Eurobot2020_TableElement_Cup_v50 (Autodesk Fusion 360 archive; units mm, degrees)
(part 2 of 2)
sketch "Sketch1" plane through (0, 0, 0) normal (1, 0, 0) x axis (0, 1, 0)
  line L1 (0, 5.6673) -> (0, 0)
  line L2 (0, 150) -> (0, 5.6673)
  line L3 (150, 0) -> (-150, 0)
  line L4 (0, -150) -> (0, 0)
  line L5 (25, -137.7498) -> (25, 137.7498)
  line L6 (-25, -137.7498) -> (-25, 137.7498)
  line L7 (15, -139.1941) -> (15, 139.1941)
  line L8 (-15, 139.1941) -> (-15, -139.1941)
  line L9 (15, 20) -> (-15, 20)
  line L10 (-15, -20) -> (15, -20)
  circle C1 centre (0, 0) radius 150
  arc A1 centre (0, 0) radius 140 clockwise from (-15, 139.1941) to (15, 139.1941)
  arc A2 centre (0, 0) radius 140 clockwise from (-25, -137.7498) to (-25, 137.7498)
  arc A3 centre (0, 0) radius 140 clockwise from (25, 137.7498) to (25, -137.7498)
  arc A4 centre (0, 0) radius 140 clockwise from (15, -139.1941) to (-15, -139.1941)
  point P1 (0, 0)
  point P2 (0, 0)
  point P3 (0, 0)
  point P5 (0, 150)
  point P6 (-150, 0)
  point P7 (150, 0)
  point P10 (0, 77.8337)
  point P11 (0, 0)
  point P12 (0, -150)
  point P13 (0, 0)
  point P18 (0, 0)
  point P17 (-25, -137.7498)
  point P19 (-25, -137.7498)
  point P20 (0, 0)
  point P15 (25, -137.7498)
  point P21 (25, -137.7498)
  point P24 (0, -75)
  point P25 (0, 0)
  point P26 (-15, 20)
  point P27 (15, 20)
  point P28 (15, -20)
  point P29 (-15, -20)
  coincident P1 P2
  coincident P1 P3
  vertical L1
  coincident C1 P5
  parallel L1 L2
  coincident C1 P6
  coincident C1 P7
  horizontal L3
  coincident P2 L3
  midpoint L2 P10
  coincident P2 P11
  coincident C1 P12
  perpendicular L3 L4
  coincident P1 P13
  vertical L6
  coincident P2 P18
  coincident P17 P19
  coincident P2 P20
  coincident P15 P21
  equal A1 A2
  equal A1 A3
  midpoint L4 P24
  coincident P2 P25
  tangent A3 A4
  perpendicular L3 L7
  parallel L6 L8
  coincident L8 P26
  coincident L7 P27
  perpendicular L7 L9
  coincident L7 P28
  coincident L8 P29
  perpendicular L8 L10
  dimension "d1" diameter C1 = 300
  dimension "d11" distance C1 A3 = 10
  dimension "d13" distance L5 L7 = 10
  dimension "d14" distance L6 L8 = 10
  dimension "d15" distance P18 L7 = 15
  dimension "d16" distance P20 L8 = 15
  dimension "d17" distance P13 L10 = 20
  dimension "d18" distance P2 L9 = 20
extrude "Extrude1" new body sketch "Sketch1" profile of C1 A1 L5 L6 A2 A3 A4 L7 L8 L9 L10 along normal blind 20
extrude "Extrude1" new body sketch "Sketch1" profile of C1 A1 L5 L6 A2 A3 A4 L7 L8 L9 L10 against normal blind 3
extrude "Extrude1" sketch "Sketch1" profile of C1 A1 L5 L6 A2 A3 A4 L7 L8 L9 L10 blind 3
as_built_joint "As-built1"
hole "Hole1" HoleDepth 70 HoleDiameter 7 TipAngle 118
sketch "Sketch3" plane through (0, 0, 0) normal (1, 0, 0) x axis (0, 1, 0)
  point P1 (0, 0)
  point P2 (0, 0)
  coincident P1 P2
hole "Hole2" HoleDepth 70 HoleDiameter 6 TipAngle 118
sketch "Sketch1" plane through (23, 0, 0) normal (1, 0, 0) x axis (0, 1, 0)
  circle C1 centre (0, 0) radius 150
  point P1 (0, 0)
  point P3 (0, 0)
  coincident P1 P3
hole "Hole2" HoleDepth 70 HoleDiameter 6 TipAngle 118 CSDiameter 14 CSAngle 90
sketch "Sketch2" plane through (0, 0, 0) normal (1, 0, 0) x axis (0, 1, 0)
  circle C1 centre (0, 0) radius 3.5
  circle C2 centre (0, 0) radius 2
  point P1 (0, 0)
  point P2 (0, 0)
  coincident P1 P2
  concentric C1 C2
  dimension "d55" diameter C1 = 7
  dimension "d56" diameter C2 = 4
extrude "Extrude1" new body sketch "Sketch2" along normal blind 20
as_built_joint "As-built2"
sketch "Sketch1" plane through (0, 0, 0) normal (0, 1, 0) x axis (1, 0, 0)
  line L1 (22.3531, 0) -> (-23.5815, 0)
  line L2 (22.3531, -4.2842) -> (22.3531, 0)
  line L3 (20, -1.7) -> (22.3531, -4.2842)
  line L4 (-23.5815, -1.7) -> (20, -1.7)
  line L5 (-23.5815, 0) -> (-23.5815, -1.7)
  line L6 (20, -150) -> (20, 150)
  point P1 (0, 0)
  point P5 (20, -1.7)
  horizontal L1
  perpendicular L1 L2
  perpendicular L2 L4
  coincident P1 L1
  coincident P5 L6
  vertical L5
  dimension "d59" distance L1 L4 = 1.7
revolve "Revolve1" sketch "Sketch1" AlongAngle 360
thread "Thread1" ThreadOffset 0 ThreadLength 21
sketch "Sketch2" plane through (0, 0, 0) normal (0, 1, 0) x axis (1, 0, 0)
  line L1 (-13.9609, -1.9748) -> (-23.5815, 0)
  line L2 (-23.5815, -1.9748) -> (-13.9609, -1.9748)
  line L3 (-23.5815, 0) -> (-23.5815, -1.9748)
  line L4 (-23.5815, 0) -> (0, 0)
  line L5 (-23.5815, 0.8397) -> (-23.5815, -0.8535)
  point P1 (0, 0)
  point P5 (0, 0)
  point P2 (-23.5815, 0)
  vertical L3
  horizontal L2
  coincident P1 P5
  horizontal L4
  coincident P2 L5
revolve "Revolve2" sketch "Sketch2" AlongAngle 360
offset_faces "OffsetFaces2" distance -0.43
offset_faces "OffsetFaces3" distance -1
sketch "Sketch3" plane through (22.3531, 0, 0) normal (1, 0, 0) x axis (0, 1, 0)
  line L1 (0, 2) -> (0, 0)
  line L2 (-0.4, 2) -> (0, 2)
  line L3 (-0.4, 0.4) -> (-0.4, 2)
  line L4 (-2, 0.4) -> (-0.4, 0.4)
  line L5 (-2, 0) -> (-2, 0.4)
  line L6 (0, 0) -> (-2, 0)
  line L7 (0.4, 0.4) -> (0.4, 2)
  line L8 (2, 0.4) -> (0.4, 0.4)
  line L9 (2, 0) -> (2, 0.4)
  line L10 (0.4, 2) -> (0, 2)
  line L11 (0.4, -2) -> (0, -2)
  line L12 (0.4, -0.4) -> (0.4, -2)
  line L13 (2, -0.4) -> (0.4, -0.4)
  line L14 (2, 0) -> (2, -0.4)
  line L15 (-0.4, -2) -> (0, -2)
  line L16 (-0.4, -0.4) -> (-0.4, -2)
  line L17 (-2, -0.4) -> (-0.4, -0.4)
  line L18 (-2, 0) -> (-2, -0.4)
  circle C1 centre (0, 0) radius 2.7989
  point P2 (0, 0)
  point P3 (0, 0)
  point P4 (0, 2)
  point P13 (0, 2)
  point P5 (-0.4, 2)
  point P9 (0.4, 2)
  point P6 (-0.4, 0.4)
  point P10 (0.4, 0.4)
  point P7 (-2, 0.4)
  point P11 (2, 0.4)
  point P8 (-2, 0)
  point P12 (2, 0)
  point P19 (0, -2)
  point P20 (-0.4, -2)
  point P21 (-0.4, -0.4)
  point P22 (-2, -0.4)
  point P23 (-2, 0)
  point P15 (0.4, -2)
  point P16 (0.4, -0.4)
  point P17 (2, -0.4)
  point P18 (2, 0)
  point P14 (0, -2)
  coincident P2 P3
  vertical L1
  perpendicular L1 L2
  perpendicular L2 L3
  perpendicular L1 L4
  perpendicular L2 L5
  horizontal L6
  equal L1 L6
  equal L2 L5
  symmetric P4 L1 P13
  symmetric L1 P5 P9
  symmetric L1 P6 P10
  symmetric L1 P7 P11
  symmetric L1 P8 P12
  symmetric P4 L6 P19
  symmetric P5 L6 P20
  symmetric P6 L6 P21
  symmetric P7 L6 P22
  symmetric P8 L6 P23
  symmetric L6 P9 P15
  symmetric L6 P10 P16
  symmetric L6 P11 P17
  symmetric L6 P12 P18
  symmetric L6 P13 P14
  dimension "d69" distance P4 P5 = 0.4
  dimension "d70" distance P7 P8 = 0.4
  dimension "d71" distance P3 P4 = 2
extrude "Extrude2" cut sketch "Sketch3" profile of L2 L3 L4 L5 L7 L8 L9 L10 L11 L12 L13 L14 L15 L16 L17 L18 against normal blind 1 taper -25
joint "Assemble1" alignAngle 0 alignOffsetX 0 alignOffsetY 0 alignOffsetZ 0.5
sketch "Sketch1" plane through (-3, 0, 0) normal (-1, 0, 0) x axis (0, -1, 0)
  circle C1 centre (0, 0) radius 3
  circle C2 centre (0, 0) radius 150
  circle C3 centre (0, 0) radius 5
  circle C4 centre (0, 0) radius 2
  point P1 (0, 0)
  point P3 (0, 0)
  coincident P1 P3
  concentric C1 C4
  dimension "d86" diameter C4 = 4
  dimension "d87" diameter C3 = 10
extrude "Extrude1" new body sketch "Sketch1" profile of C1 C3 C4 along normal blind 0.8
extrude "Extrude2" new body of existing geometry blind 0.8
as_built_joint "As-built3"
sketch "Sketch1" plane through (23, 0, 0) normal (1, 0, 0) x axis (0, 1, 0)
  circle C1 centre (0, 0) radius 150
extrude "Extrude1" new body sketch "Sketch1" along normal blind 0.3
decal "Decal1"
sketch "Sketch1" plane through (0, 0, 0) normal (1, 0, 0) x axis (0, 1, 0)
  line L1 (0, 32.5) -> (0, 0)
  line L2 (0, -127.5) -> (0, 0)
  line L3 (-15, 20) -> (15, 20)
  circle C1 centre (0, 32.5) radius 12.5
  circle C2 centre (0, -127.5) radius 12.5
  arc A1 centre (0, 0) radius 140 clockwise from (15, -139.1941) to (-15, -139.1941)
  point P1 (0, 0)
  point P2 (0, 0)
  point P3 (0, 32.5)
  point P4 (0, 32.5)
  point P5 (0, 0)
  point P6 (0, -127.5)
  point P7 (0, -127.5)
  point P8 (0, -140)
  point P9 (0, 20)
  coincident P1 P2
  vertical L1
  coincident P3 P4
  coincident P1 P5
  parallel L1 L2
  coincident P6 P7
  equal C1 C2
  coincident C2 P8
  coincident C1 P9
  coincident L1 P9
  coincident P9 L3
  coincident L2 P8
  coincident P8 A1
  dimension "d94" diameter C1 = 25
extrude "Extrude1" new body sketch "Sketch1" profile of C1 C2 along normal blind 18
as_built_joint "As-built4"
split_face "SplitFace1"
split_face "SplitFace1"
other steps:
split_face "SplitFace1"
split_face "SplitFace1"
create_component "CreateComponent1"
create_component "CreateComponent2"
create_component "CreateComponent3"
create_component "CreateComponent4"
create_component "CreateComponent5"
joint_origin "JointOrigin1" OffsetX 0 OffsetY 0 OffsetZ 0 AngleZ 0
joint_origin "JointOrigin1" OffsetX 0 OffsetY 0 OffsetZ 0 AngleZ 0
create_component "CreateComponent6"
create_component "CreateComponent7"
create_component "CreateComponent8"

design "Edge Beacon Right" references "EdgeBeacons_Base", "EdgeBeacons_LargeBorder", "EdgeBeacons_SmallBorder"
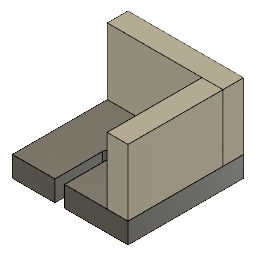
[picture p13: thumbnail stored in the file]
component_insert "Component Insert1"
ground "Ground1"
component_insert "Component Insert2"
component_insert "Component Insert4"
joint "Assemble1" OffsetX 0 OffsetY 0 OffsetZ 0 AngleZ 0 OffsetX 0 OffsetY 0 OffsetZ 0 AngleZ 0 alignAngle -90 alignOffsetX 0 alignOffsetY 0 alignOffsetZ 0
joint "Assemble2" OffsetX 0 OffsetY 0 OffsetZ 0 AngleZ 0 OffsetX 0 OffsetY 0 OffsetZ 0 AngleZ 0 alignAngle 0 alignOffsetX 0 alignOffsetY 0 alignOffsetZ 0

design "MiddleBeaconTop"
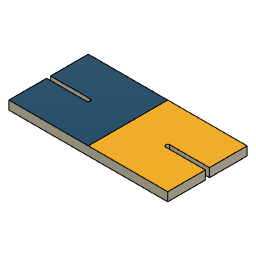
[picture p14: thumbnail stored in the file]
work_plane "WorkPlane1" AlongDistance 1000
sketch "Sketch1" plane through (0, 1000, 0) normal (0, 1, 0) x axis (1, 0, 0)
  line L1 (200, -100) -> (-200, -100)
  line L2 (200, 100) -> (200, -100)
  line L3 (-200, 100) -> (200, 100)
  line L4 (-200, -100) -> (-200, 100)
  line L5 (200, 100) -> (-200, -100)
  line L6 (-200, 100) -> (200, -100)
  line L7 (-100, -5) -> (-200, -5)
  line L8 (-200, 5) -> (-100, 5)
  line L9 (-100, 0) -> (-200, 0)
  line L10 (100, 5) -> (200, 5)
  line L11 (200, -5) -> (100, -5)
  line L12 (100, 0) -> (200, 0)
  arc A1 centre (-100, 0) radius 5 clockwise from (-100, 5) to (-100, -5)
  arc A2 centre (-200, 0) radius 5 clockwise from (-200, -5) to (-200, 5)
  arc A3 centre (100, 0) radius 5 clockwise from (100, -5) to (100, 5)
  arc A4 centre (200, 0) radius 5 clockwise from (200, 5) to (200, -5)
  point P6 (0, 0)
  point P1 (0, 0)
  point P11 (-200, 0)
  point P17 (200, 0)
  point P4 (200, 100)
  point P5 (-200, 100)
  point P3 (200, -100)
  point P12 (-100, 0)
  perpendicular L1 L2
  parallel L1 L3
  parallel L2 L4
  horizontal L1
  coincident L5 P6
  coincident L6 P6
  coincident P1 P6
  tangent L7 A1
  tangent A1 L8
  parallel L7 L8
  tangent L8 A2
  tangent L7 A2
  perpendicular L4 L9
  midpoint L4 P11
  tangent L10 A3
  tangent A3 L11
  parallel L10 L11
  tangent L11 A4
  tangent L10 A4
  perpendicular L2 L12
  midpoint L2 P17
  equal A1 A3
  equal L9 L12
  dimension "d2" distance P4 P5 = 400
  dimension "d3" distance P3 P4 = 200
  dimension "d4" distance P11 P12 = 100
  dimension "d5" radius A1 = 5
extrude "Extrude1" new body sketch "Sketch1" profile of L1 L2 L3 L4 L7 A1 L8 L10 A3 L11 against normal blind 22
work_plane "WorkPlane2"
split_face "SplitFace1"

design "MiddleBeaconVertSupport2"
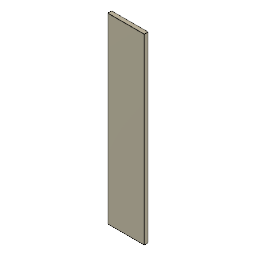
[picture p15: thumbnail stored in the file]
sketch "Sketch1"
  dimension "d1" = 1000
  dimension "d2" = 200
extrude "Extrude1" new body sketch "Sketch1" distance 22

design "manchonBleu"
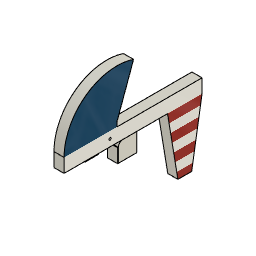
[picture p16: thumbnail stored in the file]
sketch "Sketch1" plane through (0, 0, 0) normal (1, 0, 0) x axis (0, 1, 0)
  line L1 (15, 15) -> (15, 25)
  line L2 (200, 15) -> (15, 15)
  line L3 (-100, -15) -> (125, -15)
  line L4 (-100, 15) -> (-100, -15)
  line L5 (200, 15) -> (200, -15)
  line L6 (177.5, -150) -> (200, -15)
  line L7 (147.5, -150) -> (177.5, -150)
  line L8 (125, -15) -> (147.5, -150)
  line L9 (0, 0) -> (200, 0)
  line L10 (15, 15) -> (-15, 15)
  line L11 (0, 15) -> (0, 0)
  line L12 (51.101, 124.1866) -> (15, 25)
  circle C1 centre (0, 0) radius 2.5
  circle C2 centre (15, 15) radius 115
  point P1 (0, 0)
  point P2 (0, 0)
  point P13 (200, 0)
  point P14 (0, 0)
  point P15 (0, 0)
  point P16 (0, 15)
  point P9 (-100, 15)
  point P5 (15, 15)
  point P17 (15, 15)
  point P18 (51.101, 124.1866)
  point P7 (125, -15)
  point P10 (200, -15)
  point P11 (177.5, -150)
  point P12 (147.5, -150)
  point P8 (-100, -15)
  point P4 (15, 25)
  coincident P1 P2
  perpendicular L1 L2
  horizontal L3
  perpendicular L3 L4
  vertical L5
  equal L4 L5
  parallel L3 L7
  equal L6 L8
  midpoint L5 P13
  coincident P1 P14
  horizontal L9
  coincident P1 P15
  midpoint L10 P16
  vertical L11
  coincident L2 P9
  horizontal L2
  horizontal L10
  equal L4 L10
  coincident P5 P17
  coincident P9 C2
  coincident C2 P18
  dimension "d1" diameter C1 = 5
  dimension "d2" distance P1 L4 = 100
  dimension "d4" distance P2 L5 = 200
  dimension "d8" distance P7 P10 = 75
  dimension "d9" distance P11 P12 = 30
  dimension "d11" distance P8 P9 = 30
  dimension "d12" distance P4 P5 = 10
  dimension "d22" distance L7 L9 = 150
  dimension "d23" angle L2 L12 = 70
  dimension "d36" OffsetX = 0
  dimension "d37" OffsetY = 0
  dimension "d38" OffsetZ = 0
  dimension "d39" AngleZ = 0
  dimension "d48" OffsetX = 0
  dimension "d49" OffsetY = 0
  dimension "d50" OffsetZ = 0
  dimension "d51" AngleZ = 0
extrude "Extrude1" new body sketch "Sketch1" profile of C1 L1 L2 L3 L4 L5 L6 L7 L8 C2 L12 along normal blind 22
sketch "Sketch1" plane through (0, 0, 0) normal (1, 0, 0) x axis (0, 0, -1)
  line L1 (55, 15) -> (15, 15)
  line L2 (55, 55) -> (55, 15)
  line L3 (15, 55) -> (55, 55)
  line L4 (15, 15) -> (15, 55)
  line L5 (15, -100) -> (15, 125)
  line L6 (25, 15) -> (15, 15)
  arc A1 centre (25, 25) radius 10 clockwise from (25, 15) to (15, 25)
  point P8 (25, 15)
  point P9 (15, 25)
  point P1 (0, 0)
  horizontal L1
  vertical L2
  horizontal L3
  vertical L4
  coincident L1 P8
  perpendicular L5 L6
  tangent L6 A1
  coincident L4 P9
  tangent L4 A1
  dimension "d24" distance P1 L1 = 15
  dimension "d25" distance P1 L4 = 15
  dimension "d26" distance P1 L5 = 15
  dimension "d27" distance L4 P8 = 10
  dimension "d28" distance L1 L3 = 40
  dimension "d29" distance L2 L4 = 40
  dimension "d32" OffsetX = 0
  dimension "d33" OffsetY = 0
  dimension "d34" OffsetZ = 0
  dimension "d35" AngleZ = 0
  dimension "d44" OffsetX = 0
  dimension "d45" OffsetY = 0
  dimension "d46" OffsetZ = 0
  dimension "d47" AngleZ = 0
extrude "Extrude1" new body sketch "Sketch1" profile of L1 L2 L3 L4 L5 A1 along normal blind 22
joint "Assemble1" alignAngle 0 alignOffsetX -25 alignOffsetY -28 alignOffsetZ 0
decal "Decal1"
decal "Decal2"
sketch "Sketch1" plane through (0, 18, 0) normal (0, -1, 0) x axis (1, 0, 0)
  line L1 (0, -55) -> (0, -25)
  line L2 (22, -55) -> (0, -55)
  line L3 (22, -25) -> (22, -55)
  line L4 (0, -25) -> (22, -25)
extrude "Extrude1" new body sketch "Sketch1" along normal blind 1.5 named "d52_1"
sketch "Sketch2" plane through (0, 0, -15) normal (0, 0, -1) x axis (1, 0, 0)
  line L1 (0, -125) -> (0, 100)
  line L2 (22, -125) -> (0, -125)
  line L3 (22, 100) -> (22, -125)
  line L4 (0, 100) -> (22, 100)
  line L5 (0, 55) -> (0, 25)
  line L6 (22, 55) -> (0, 55)
  line L7 (22, 25) -> (22, 55)
  line L8 (0, 25) -> (22, 25)
extrude "Extrude2" new body sketch "Sketch2" profile of L1 L3 L5 L6 L7 L8 along normal blind 1.5 named "d63_1"
joint_origin "JointOrigin1" OffsetX 0 named "d66_1" OffsetY 0 named "d67_1" OffsetZ 0 named "d68_1" AngleZ 0 named "d69_1"
joint_origin "JointOrigin2" OffsetX 0 named "d78_1" OffsetY 0 named "d79_1" OffsetZ 0 named "d80_1" AngleZ 0 named "d81_1"
remove_body "RemoveBody1"
joint "Assemble2" alignAngle 0 alignOffsetX 0 alignOffsetY 0 alignOffsetZ 0
base_feature "Base Feature"
joint "Assemble3" alignAngle 0 alignOffsetX 0 alignOffsetY 45 alignOffsetZ 0
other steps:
create_component "CreateComponent1"
create_component "CreateComponent2"
joint_origin "JointOrigin3" OffsetX 0 OffsetY 0 OffsetZ 0 AngleZ 0
joint_origin "JointOrigin3" OffsetX 0 OffsetY 0 OffsetZ 0 AngleZ 0
create_component "CreateComponent3"
joint_origin "JointOrigin1" OffsetX 0 OffsetY 0 OffsetZ 0 AngleZ 0
joint_origin "JointOrigin3" OffsetX 0 OffsetY 0 OffsetZ 0 AngleZ 0
joint_origin "JointOrigin4" OffsetX 0 OffsetY 0 OffsetZ 0 AngleZ 0
joint_origin "JointOrigin4" OffsetX 0 OffsetY 0 OffsetZ 0 AngleZ 0

design "Rocher"
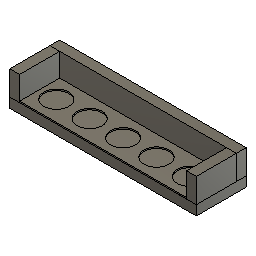
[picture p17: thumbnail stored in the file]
sketch "Sketch1" plane through (0, 0, 0) normal (0, 1, 0) x axis (1, 0, 0)
  line L1 (209.5, 0) -> (-209.5, 0)
  line L2 (209.5, 112) -> (209.5, 0)
  line L3 (-209.5, 112) -> (209.5, 112)
  line L4 (-209.5, 0) -> (-209.5, 112)
  point P6 (0, 0)
  horizontal L1
  vertical L2
  horizontal L3
  vertical L4
  coincident L1 P6
  dimension "d11" distance L2 L4 = 419 (= "375 mm + ( ( 22 * 2 ) * 1 mm )")
  dimension "d12" distance L2 P6 = 209.5 (= "d11 / 2")
  dimension "d13" distance L1 L3 = 112 (= "90 mm + 22 mm")
extrude "Extrude1" new body sketch "Sketch1" against normal blind 22
sketch "Sketch1" plane through (0, 0, 0) normal (0, 1, 0) x axis (-1, 0, 0)
  line L1 (-209.5, -112) -> (209.5, -112)
  line L2 (-209.5, -90) -> (-209.5, -112)
  line L3 (209.5, -90) -> (-209.5, -90)
  line L4 (209.5, -112) -> (209.5, -90)
  line L5 (-209.5, -112) -> (-209.5, 0)
  line L6 (209.5, 0) -> (209.5, -112)
  line L7 (209.5, -112) -> (-209.5, -112)
  horizontal L1
  vertical L2
  horizontal L3
  vertical L4
  collinear L2 L5
  collinear L4 L6
  collinear L1 L7
  dimension "d17" distance L1 L3 = 22
extrude "Extrude1" new body sketch "Sketch1" along normal blind 55
sketch "Sketch1" plane through (0, 0, 0) normal (0, 1, 0) x axis (-1, 0, 0)
  line L1 (-147, 0) -> (147, 0)
  line L2 (147, -90) -> (125, -90)
  line L3 (147, 0) -> (147, -90)
  line L4 (125, 0) -> (147, 0)
  line L5 (125, -90) -> (125, 0)
  line L6 (-147, 0) -> (147, 0)
  line L7 (147, -112) -> (-147, -112)
  line L8 (147, 0) -> (147, -112)
  line L9 (147, -90) -> (-147, -90)
  line L10 (147, 0) -> (147, -112)
  line L11 (-147, -112) -> (-147, 0)
  line L12 (147, -112) -> (-147, -112)
  horizontal L2
  vertical L3
  horizontal L4
  vertical L5
  collinear L4 L6
  collinear L3 L8
  collinear L2 L9
  dimension "d20" distance L3 L5 = 22
extrude "Extrude1" new body sketch "Sketch1" profile of L1 L2 L3 L4 L5 L6 L8 L9 L10 along normal blind 55
sketch "Sketch1" plane through (0, 0, 0) normal (0, 1, 0) x axis (-1, 0, 0)
  line L1 (209.5, 0) -> (209.5, -112)
  line L2 (-209.5, 0) -> (209.5, 0)
  line L3 (-209.5, -112) -> (-209.5, 0)
  line L4 (209.5, -112) -> (-209.5, -112)
  line L5 (-187.5, -90) -> (-209.5, -90)
  line L6 (-187.5, 0) -> (-187.5, -90)
  line L7 (-209.5, 0) -> (-187.5, 0)
  line L8 (-209.5, -90) -> (-209.5, 0)
  line L9 (209.5, -90) -> (-209.5, -90)
  horizontal L5
  vertical L6
  horizontal L7
  vertical L8
  collinear L2 L7
  collinear L5 L9
  collinear L3 L8
  dimension "d23" distance L6 L8 = 22
extrude "Extrude1" new body sketch "Sketch1" profile of L2 L3 L5 L6 L7 L8 L9 along normal blind 55
joint "Assemble1" alignAngle 0 alignOffsetX 0 alignOffsetY 0 alignOffsetZ 0
joint "Assemble2" alignAngle 0 alignOffsetX 0 alignOffsetY 0 alignOffsetZ 0
joint "Assemble3" alignAngle 0 alignOffsetX 0 alignOffsetY 0 alignOffsetZ 0
ground "Ground1"
sketch "Sketch1" plane through (0, 0, 0) normal (0, 1, 0) x axis (-1, 0, 0)
  line L1 (209.5, 0) -> (209.5, -112)
  line L2 (-209.5, 0) -> (209.5, 0)
  line L3 (-209.5, -112) -> (-209.5, 0)
  line L4 (209.5, -112) -> (-209.5, -112)
  line L5 (-209.5, -90) -> (209.5, -90)
  line L6 (187.5, -90) -> (187.5, 0)
  line L7 (-187.5, 0) -> (-187.5, -90)
  circle C1 centre (150, -45) radius 28
  circle C2 centre (75, -45) radius 28
  circle C3 centre (0, -45) radius 28
  circle C4 centre (-75, -45) radius 28
  circle C5 centre (-150, -45) radius 28
  point P12 (150, -45)
  point P13 (75, -45)
  point P14 (0, -45)
  point P15 (-75, -45)
  point P16 (-150, -45)
  dimension "d62" diameter C1 = 56
  dimension "d67" distance L6 P12 = 37.5
  dimension "d68" distance P12 P13 = 75 (= "d67 * 2")
  dimension "d69" distance P13 P14 = 75 (= "d68")
  dimension "d70" distance P14 P15 = 75 (= "d69")
  dimension "d72" distance L2 P12 = 45
  dimension "d73" distance L2 P13 = 45
  dimension "d74" distance L2 P14 = 45
  dimension "d75" distance L2 P15 = 45
  dimension "d90" diameter C5 = 56 (= "d62")
  dimension "d91" distance P15 P16 = 75
  dimension "d92" distance L7 P16 = 37.5
  dimension "d93" diameter C2 = 56 (= "d62")
  dimension "d94" diameter C3 = 56 (= "d62")
  dimension "d95" diameter C4 = 56
extrude "Extrude1" new body sketch "Sketch1" profile of L2 L5 L6 L7 C1 C2 C3 C4 C5 along normal blind 3
joint "Assemble4" alignAngle 180 alignOffsetX 0 alignOffsetY 0 alignOffsetZ 0
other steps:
create_component "CreateComponent1"
create_component "CreateComponent2"
create_component "CreateComponent3"
create_component "CreateComponent4"
joint_origin "JointOrigin1" OffsetX 0 OffsetY 0 OffsetZ 0 AngleZ 0
joint_origin "JointOrigin1" OffsetX 0 OffsetY 0 OffsetZ 0 AngleZ 0
joint_origin "JointOrigin1" OffsetX 0 OffsetY 0 OffsetZ 0 AngleZ 0
joint_origin "JointOrigin2" OffsetX 0 OffsetY 0 OffsetZ 0 AngleZ 0
joint_origin "JointOrigin1" OffsetX 0 OffsetY 0 OffsetZ 0 AngleZ 0
joint_origin "JointOrigin3" OffsetX 0 OffsetY 0 OffsetZ 0 AngleZ 0
create_component "CreateComponent5"
joint_origin "JointOrigin1" OffsetX 0 OffsetY 0 OffsetZ 0 AngleZ 0
joint_origin "JointOrigin2" OffsetX 0 OffsetY 0 OffsetZ 0 AngleZ 0

design "Balise Rouge"
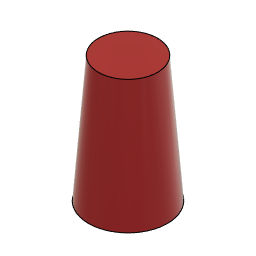
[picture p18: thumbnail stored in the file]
sketch "Sketch1" plane through (0, 0, 0) normal (1, 0, 0) x axis (0, 0, -1)
  line L1 (-36, 0) -> (0, 0)
  line L2 (-27, 115) -> (-36, 0)
  line L3 (0, 115) -> (-27, 115)
  line L4 (0, 0) -> (0, 115)
  line L5 (-25.6128, 113.5) -> (0, 113.5)
  line L6 (-34.4954, 0) -> (-25.6128, 113.5)
  line L7 (0, 0) -> (-34.4954, 0)
  point P1 (0, 0)
  point P2 (0, 0)
  point P6 (0, 0)
  point P7 (0, 113.5)
  point P10 (0, 0)
  point P4 (-27, 115)
  point P5 (0, 115)
  point P3 (-36, 0)
  coincident P1 P2
  horizontal L1
  parallel L1 L3
  coincident P1 P6
  perpendicular L1 L4
  coincident L4 P7
  perpendicular L4 L5
  coincident L4 P10
  perpendicular L4 L7
  collinear L1 L7
  parallel L2 L6
  dimension "d1" distance P4 P5 = 27 (= "( 54 / 2 ) * 1 mm")
  dimension "d2" distance L1 L3 = 115
  dimension "d3" distance P2 P3 = 36 (= "( 72 / 2 ) * 1 mm")
  dimension "d5" distance L3 L5 = 1.5
  dimension "d6" distance L2 L6 = 1.5
revolve "Revolve1" sketch "Sketch1" AlongAngle 360

design "taquet"
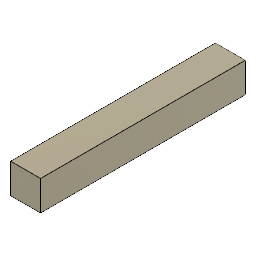
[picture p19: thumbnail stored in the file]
sketch "Sketch1" plane through (0, 0, 0) normal (0, 1, 0) x axis (1, 0, 0)
  line L1 (11, 150) -> (-11, 150)
  line L2 (11, 0) -> (11, 150)
  line L3 (11, 150) -> (-11, 0)
  line L4 (-11, 150) -> (-11, 0)
  point P1 (0, 0)
  horizontal L1
  vertical L2
  horizontal L3
  vertical L4
  coincident P1 L3
  dimension "d1" distance L2 L4 = 22
  dimension "d2" distance P1 L4 = 11 (= "d1 / 2")
  dimension "d3" = 150
extrude "Extrude1" new body sketch "Sketch1" along normal blind 22

design "ROUE_MINI_V3_ASSEMBLAGE" references "ROUE_V3"
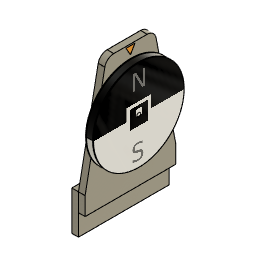
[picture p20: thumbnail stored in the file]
sketch "Sketch1" plane through (0, 0, 0) normal (1, 0, 0) x axis (0, 1, 0)
  line L1 (-150, 0) -> (0, 0)
  line L2 (0, 420) -> (-80, 420)
  line L3 (0, 0) -> (0, 420)
  line L4 (-150, 60) -> (-80, 420)
  line L5 (-150, 0) -> (-150, 60)
  line L6 (150, 0) -> (0, 0)
  line L7 (150, 0) -> (150, 60)
  line L8 (150, 60) -> (80, 420)
  line L9 (0, 420) -> (80, 420)
  point P1 (0, 0)
  point P2 (0, 0)
  point P6 (0, 0)
  point P8 (0, 0)
  point P3 (-150, 0)
  point P9 (150, 0)
  point P4 (-80, 420)
  point P11 (80, 420)
  point P5 (0, 420)
  point P12 (0, 420)
  point P7 (-150, 60)
  point P10 (150, 60)
  point P13 (0, 230)
  coincident P1 P2
  horizontal L1
  parallel L1 L2
  coincident P1 P6
  perpendicular L1 L3
  perpendicular L1 L5
  symmetric P2 L3 P8
  symmetric P3 L3 P9
  symmetric P4 L3 P11
  symmetric P5 L3 P12
  symmetric L3 P7 P10
  coincident L3 P13
  dimension "d1" distance P2 P3 = 150
  dimension "d2" distance P4 P5 = 80
  dimension "d3" distance P3 P7 = 60
  dimension "d4" distance L1 L2 = 420
  dimension "d5" distance L6 P13 = 230
extrude "Extrude1" new body sketch "Sketch1" profile of L1 L2 L4 L5 L6 L7 L8 L9 along normal blind 22
hole "Hole1" HoleDepth 100 HoleDiameter 3 TipAngle 118
fillet "Fillet1" radius 30
sketch "Sketch1" plane through (0, 0, 0) normal (-1, 0, 0) x axis (0, -1, 0)
  line L1 (-150, 60) -> (-84.7199, 395.7261)
  line L2 (-150, 0) -> (-150, 60)
  line L3 (150, 0) -> (-150, 0)
  line L4 (150, 60) -> (150, 0)
  line L5 (84.7199, 395.7261) -> (150, 60)
  line L6 (-55.2715, 420) -> (55.2715, 420)
  line L7 (-11, 213.2177) -> (-11, 0)
  line L8 (-86.7983, 136.8472) -> (-11, 136.8472)
  line L9 (-86.7983, 117.0762) -> (-86.7983, 136.8472)
  line L10 (-11, 117.0762) -> (-86.7983, 117.0762)
  line L11 (-11, 136.8472) -> (-11, 117.0762)
  line L12 (-13, 136.8472) -> (-11, 136.8472)
  line L13 (-13, 117.0762) -> (-13, 136.8472)
  line L14 (-11, 117.0762) -> (-13, 117.0762)
  line L15 (-11, 136.8472) -> (-11, 117.0762)
  circle C1 centre (0, 230) radius 1.5
  arc A1 centre (-55.2715, 390) radius 30 clockwise from (-84.7199, 395.7261) to (-55.2715, 420)
  arc A2 centre (55.2715, 390) radius 30 clockwise from (55.2715, 420) to (84.7199, 395.7261)
  point P13 (-11, 0)
  point P15 (-11, 136.8472)
  point P20 (-13, 117.0762)
  point P1 (0, 0)
  coincident L3 P13
  perpendicular L3 L7
  horizontal L8
  vertical L9
  horizontal L10
  vertical L11
  coincident L7 P15
  horizontal L12
  vertical L13
  horizontal L14
  vertical L15
  coincident L10 P20
  dimension "d31" distance L11 L13 = 2
  dimension "d32" distance P1 L7 = 11 (= "( 22 / 2 ) * 1 mm")
extrude "Extrude1" new body sketch "Sketch1" profile of L8 L9 L10 L11 L12 L13 L14 L15 along normal blind 2
extrude "Extrude2" add sketch "Sketch1" profile of L8 L10 L11 L12 L13 L14 L15 along normal blind 60
ground "Ground1"
sketch "Sketch1" plane through (0, 0, 0) normal (-1, 0, 0) x axis (0, -1, 0)
  line L1 (-150, 60) -> (-84.7199, 395.7261)
  line L2 (-150, 0) -> (-150, 60)
  line L3 (150, 0) -> (-150, 0)
  line L4 (150, 60) -> (150, 0)
  line L5 (84.7199, 395.7261) -> (150, 60)
  line L6 (-55.2715, 420) -> (55.2715, 420)
  line L7 (150, 0) -> (150, 60)
  line L8 (-150, 0) -> (-150, 60)
  line L9 (150, 60) -> (-150, 60)
  line L10 (150, -70) -> (150, 0)
  line L11 (-150, -70) -> (150, -70)
  line L12 (-150, 0) -> (-150, -70)
  circle C1 centre (0, 230) radius 1.5
  arc A1 centre (-55.2715, 390) radius 30 clockwise from (-84.7199, 395.7261) to (-55.2715, 420)
  arc A2 centre (55.2715, 390) radius 30 clockwise from (55.2715, 420) to (84.7199, 395.7261)
  point P15 (-150, 60)
  point P17 (-150, 60)
  point P13 (150, 60)
  point P18 (150, 60)
  point P14 (150, 0)
  point P19 (150, 0)
  point P7 (-150, 0)
  point P22 (-150, 0)
  point P20 (150, -70)
  coincident P15 P17
  coincident P13 P18
  coincident P14 P19
  perpendicular L3 L10
  perpendicular L10 L11
  coincident P7 P22
  vertical L12
  dimension "d37" distance P19 P20 = 70
extrude "Extrude1" new body sketch "Sketch1" profile of L2 L3 L4 L7 L8 L9 L10 L11 L12 along normal blind 22
joint "Assemble2" alignAngle 0 alignOffsetX 0 alignOffsetY 0 alignOffsetZ 0
joint "Assemble3" alignAngle 0 alignOffsetX 0 alignOffsetY 0 alignOffsetZ 0
sketch "Sketch1" plane through (22, 0, 0) normal (1, 0, 0) x axis (0, 1, 0)
  line L1 (-55.2715, 420) -> (55.2715, 420)
  line L2 (-150, 60) -> (-84.7199, 395.7261)
  line L3 (-150, 0) -> (-150, 60)
  line L4 (150, 0) -> (-150, 0)
  line L5 (150, 60) -> (150, 0)
  line L6 (84.7199, 395.7261) -> (150, 60)
  line L7 (0, 389.0192) -> (0, 420)
  line L8 (-15, 415) -> (0, 389.0192)
  line L9 (15, 415) -> (-15, 415)
  line L10 (0, 389.0192) -> (15, 415)
  arc A1 centre (55.2715, 390) radius 30 clockwise from (55.2715, 420) to (84.7199, 395.7261)
  arc A2 centre (-55.2715, 390) radius 30 clockwise from (-84.7199, 395.7261) to (-55.2715, 420)
  circle C1 centre (0, 230) radius 1.5
  point P13 (0, 420)
  point P14 (0, 389.0192)
  point P16 (15, 415)
  midpoint L1 P13
  perpendicular L1 L7
  perpendicular L7 L9
  equal L8 L10
  equal L8 L9
  dimension "d64" distance L1 L9 = 5
  dimension "d66" distance P14 P16 = 30
extrude "Extrude1" new body sketch "Sketch1" profile of L8 L9 L10 along normal blind 0.2
ground "Ground2"
ground "Ground3"
component_insert "Component Insert"
joint "Assemble4" OffsetX 0 OffsetY 0 OffsetZ 0 AngleZ 0 alignAngle 0 alignOffsetX 0 alignOffsetY 0 alignOffsetZ 0
ground "Ground4"
ground "Ground5"
joint "Assemble1" alignAngle 0 alignOffsetX 0 alignOffsetY -5 alignOffsetZ 0
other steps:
create_component "CreateComponent1"
create_component "CreateComponent3"
create_component "CreateComponent4"
joint_origin "JointOrigin1" OffsetX 0 OffsetY 0 OffsetZ 0 AngleZ 0
joint_origin "JointOrigin2" OffsetX 0 OffsetY 0 OffsetZ 0 AngleZ 0
joint_origin "JointOrigin2" OffsetX 0 OffsetY 0 OffsetZ 0 AngleZ 0
joint_origin "JointOrigin3" OffsetX 0 OffsetY 0 OffsetZ 0 AngleZ 0
create_component "CreateComponent1"
joint_origin "JointOrigin4" OffsetX 0 OffsetY 0 OffsetZ 0 AngleZ 0
joint_origin "JointOrigin1" OffsetX 0 OffsetY 0 OffsetZ 0 AngleZ 0
joint_origin "JointOrigin5" OffsetX 0 OffsetY 0 OffsetZ 0 AngleZ 0

design "MiddleBeaconVertSupport1"
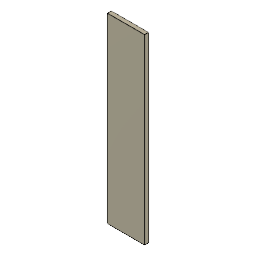
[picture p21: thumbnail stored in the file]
sketch "Sketch1"
  dimension "d1" = 978 (= "1000 mm - 22 mm")
  dimension "d2" = 200
extrude "Extrude1" new body sketch "Sketch1" distance 22

design "BorderSmall"
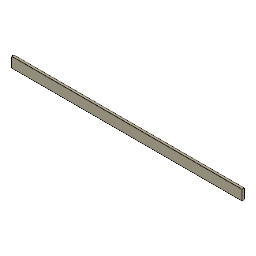
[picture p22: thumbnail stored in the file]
sketch "Sketch1" plane through (0, 0, 0) normal (0, 0, 1) x axis (1, 0, 0)
  line L1 (2044, 0) -> (0, 0)
  line L2 (2044, 92) -> (2044, 0)
  line L3 (0, 92) -> (2044, 92)
  line L4 (0, 0) -> (0, 92)
  point P1 (0, 0)
  point P2 (0, 0)
  point P3 (2044, 0)
  point P5 (0, 92)
  horizontal L1
  vertical L2
  horizontal L3
  vertical L4
  coincident P1 P2
  dimension "d1" distance P2 P3 = 2044 (= "2000 mm + 44 mm")
  dimension "d2" distance P2 P5 = 92 (= "70 mm + 22 mm")
extrude "Extrude1" new body sketch "Sketch1" along normal blind 22

design "ZoneRocheuse"
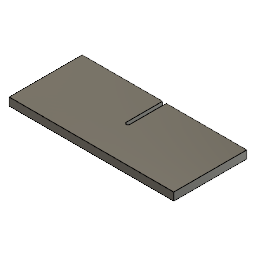
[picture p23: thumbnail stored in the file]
sketch "Sketch2" plane through (0, 0, 0) normal (0, 1, 0) x axis (1, 0, 0)
  line L1 (225, 200) -> (-225, 200)
  line L2 (225, 0) -> (225, 200)
  line L3 (-225, 0) -> (225, 0)
  line L4 (-225, 200) -> (-225, 0)
  line L5 (5, 200) -> (5, 100)
  line L6 (-5, 200) -> (-5, 100)
  circle C1 centre (0, 100) radius 5
  point P1 (0, 0)
  point P2 (0, 0)
  point P7 (0, 0)
  point P9 (5, 100)
  point P10 (5, 200)
  point P11 (-5, 100)
  point P12 (-5, 200)
  point P8 (0, 100)
  coincident P1 P2
  horizontal L1
  vertical L2
  horizontal L3
  vertical L4
  coincident L3 P7
  coincident C1 P9
  coincident L1 P10
  tangent C1 L5
  perpendicular L1 L5
  coincident C1 P11
  coincident L1 P12
  tangent C1 L6
  perpendicular L1 L6
  dimension "d19" distance L2 L4 = 450
  dimension "d20" distance L1 L3 = 200
  dimension "d21" distance L4 P7 = 225 (= "d19 / 2")
  dimension "d22" diameter C1 = 10
  dimension "d23" distance L1 P8 = 100
  dimension "d24" distance L4 P8 = 225 (= "d21")
  dimension "d9" diameter = 30
  dimension "d10" AlongDistance = 110
  dimension "d11" TaperAngle = 0
  dimension "d12" AgainstDistance = 130
  dimension "d13" Side2TaperAngle = 0
  dimension "d14" diameter = 30
  dimension "d15" AlongDistance = 125
  dimension "d16" TaperAngle = 0
  dimension "d17" AgainstDistance = 150
  dimension "d18" Side2TaperAngle = 0
extrude "Extrude2" new body sketch "Sketch2" against normal blind 22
